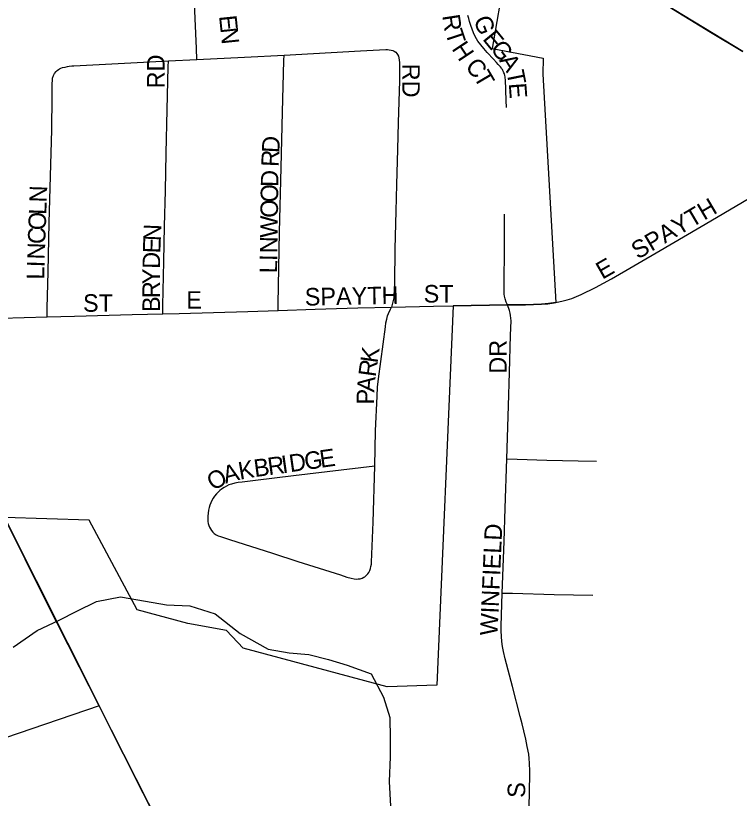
# Model space of a CAD drawing. Extents: x 0 to 34, y 0 to 22.
# Drawn here: x 6.1227 to 6.3183, y 17.9272 to 18.1386 of the extents above; entities that cross this region are included whole.
import ezdxf

# ---------------------------------------------------------------- set-up
doc = ezdxf.new("R2010")
doc.units = 0
for name, color, linetype in [('Default', 7, 'Continuous'), ('GM_X_City_Street', 7, 'Continuous'), ('GM_X_City_Street_Text', 7, 'Continuous'), ('GM_X_Corporation', 7, 'Continuous'), ('GM_X_County_Road', 7, 'Continuous'), ('GM_X_Minor_River', 7, 'Continuous'), ('GM_X_State_Route', 7, 'Continuous'), ('GM_X_Township_Subdivision', 7, 'Continuous'), ('GM_X_Township_Subdivision_Text', 7, 'Continuous')]:
    doc.layers.add(name, color=color, linetype=linetype)

msp = doc.modelspace()

# ---------------------------------------------------------------- linework, layer by layer
at = {"layer": 'Default'}
msp.add_lwpolyline([(6.21175, 17.82109), (6.19182, 17.86034), (6.14526, 17.95216), (6.11969, 18.00306), (6.11076, 18.02099), (6.07084, 18.10026), (6.06147, 18.11896), (6.05496, 18.13197), (6.04884, 18.14072), (6.02545, 18.17135), (6.01014, 18.19175), (5.98748, 18.22193), (5.95849, 18.26057), (5.9573, 18.26217)], dxfattribs=at)
at = {"layer": 'GM_X_City_Street'}
for points in [[(6.17167, 18.12678), (6.17156, 18.12969), (6.17107, 18.14192), (6.17077, 18.15276), (6.17063, 18.15636)], [(6.25541, 18.11379), (6.25532, 18.11573), (6.25509, 18.12137), (6.25506, 18.12171), (6.25501, 18.12205), (6.25494, 18.12243), (6.25481, 18.12285), (6.25469, 18.12314), (6.25456, 18.12344), (6.2544, 18.12379), (6.25426, 18.12404), (6.25412, 18.12427), (6.254, 18.12445), (6.25377, 18.12474), (6.25313, 18.12545), (6.25266, 18.12597), (6.25187, 18.12682), (6.25019, 18.12865), (6.24924, 18.12974), (6.24767, 18.1317), (6.24725, 18.13237), (6.24695, 18.13298), (6.2465, 18.13394), (6.2461, 18.13495), (6.24574, 18.13595), (6.24538, 18.137), (6.24516, 18.13786), (6.24496, 18.13869)], [(6.19525, 18.12796), (6.21596, 18.12909), (6.22102, 18.12938), (6.22275, 18.12946), (6.22323, 18.12944), (6.22368, 18.1294), (6.22418, 18.12932), (6.22464, 18.12917), (6.22506, 18.12899), (6.22543, 18.12874), (6.22576, 18.12841), (6.22596, 18.12808), (6.22617, 18.12765), (6.22628, 18.1272), (6.2264, 18.12662), (6.22648, 18.12594), (6.2265, 18.12439), (6.22643, 18.12097), (6.22608, 18.10976), (6.22592, 18.10245), (6.22567, 18.09298), (6.22547, 18.08575), (6.22521, 18.07557), (6.22507, 18.06638), (6.22495, 18.06289), (6.2249, 18.06235), (6.22478, 18.06165), (6.22432, 18.05988)], [(6.17167, 18.12678), (6.18457, 18.12741), (6.19525, 18.12796)], [(6.19363, 18.05896), (6.19366, 18.06074), (6.19404, 18.0801), (6.19448, 18.09758), (6.19482, 18.11254), (6.19521, 18.12645), (6.19525, 18.12796)], [(6.13118, 18.05725), (6.13123, 18.05961), (6.13146, 18.06938), (6.13178, 18.08262), (6.13215, 18.09528), (6.13244, 18.10779), (6.13255, 18.11667), (6.13255, 18.12037), (6.13262, 18.12103), (6.13268, 18.12168), (6.13292, 18.12247), (6.13324, 18.123), (6.13368, 18.12353), (6.13396, 18.1238), (6.13428, 18.12403), (6.13458, 18.12422), (6.13494, 18.1244), (6.1354, 18.12456), (6.13605, 18.12473), (6.13668, 18.12485), (6.13721, 18.12493), (6.13789, 18.12502), (6.13843, 18.12506), (6.15558, 18.12597), (6.164, 18.12641)], [(6.16247, 18.05805), (6.1625, 18.06034), (6.16274, 18.07222), (6.16297, 18.08172), (6.16319, 18.0913), (6.16339, 18.10146), (6.16369, 18.1132), (6.16396, 18.12481), (6.164, 18.12641)], [(6.164, 18.12641), (6.17167, 18.12678)], [(6.25562, 18.06045), (6.25532, 18.06118), (6.25499, 18.06209), (6.25483, 18.06279), (6.25479, 18.06333), (6.25488, 18.07846), (6.25481, 18.08494)], [(6.19363, 18.05896), (6.20364, 18.05927), (6.21523, 18.05966), (6.22432, 18.05988)], [(6.21975, 18.01694), (6.22001, 18.02642), (6.22038, 18.03583), (6.22055, 18.03826), (6.22075, 18.04048), (6.22264, 18.05458), (6.22281, 18.05561), (6.22301, 18.05664), (6.22326, 18.0575), (6.2235, 18.05812), (6.22403, 18.05927), (6.22432, 18.05988)], [(6.22432, 18.05988), (6.23566, 18.06016), (6.24095, 18.06026)], [(6.09569, 18.05096), (6.09827, 18.05222), (6.10041, 18.05326), (6.10209, 18.05398), (6.1039, 18.05469), (6.10489, 18.05501), (6.106, 18.05534), (6.10711, 18.05563), (6.10817, 18.05584), (6.11097, 18.05625), (6.11397, 18.05662), (6.11628, 18.05679), (6.11874, 18.05687), (6.13118, 18.05725)], [(6.13118, 18.05725), (6.1386, 18.05741), (6.1542, 18.05783), (6.16247, 18.05805)], [(6.16247, 18.05805), (6.1669, 18.05818), (6.18544, 18.0587), (6.19363, 18.05896)], [(6.21975, 18.01694), (6.19777, 18.01428), (6.18749, 18.01306), (6.18392, 18.01261), (6.18289, 18.01247), (6.18194, 18.01228), (6.18109, 18.01208), (6.18037, 18.01183), (6.17967, 18.01152), (6.17906, 18.01117), (6.17837, 18.0107), (6.17787, 18.01031), (6.17735, 18.00981), (6.17697, 18.0094), (6.17646, 18.00881), (6.1761, 18.00827), (6.17572, 18.00759), (6.17545, 18.00702), (6.17521, 18.0064), (6.17502, 18.00576), (6.17486, 18.00506), (6.17474, 18.00416), (6.17465, 18.00336), (6.17464, 18.0025), (6.17467, 18.00192), (6.17476, 18.00138), (6.17491, 18.00085), (6.17511, 18.00038), (6.17537, 17.99994), (6.17564, 17.99951), (6.17597, 17.9991), (6.17639, 17.99873), (6.17689, 17.99838), (6.17743, 17.99812), (6.17804, 17.99789), (6.1805, 17.99712), (6.19212, 17.99337), (6.19895, 17.99119), (6.21047, 17.98752), (6.21224, 17.98696), (6.21343, 17.98662), (6.21422, 17.98649), (6.21476, 17.98642), (6.21533, 17.98645), (6.2158, 17.98651), (6.21637, 17.98669), (6.21679, 17.98689), (6.21707, 17.98704), (6.21738, 17.98727), (6.21765, 17.98754), (6.2179, 17.98783), (6.21814, 17.98822), (6.21841, 17.98871), (6.21862, 17.98924), (6.21875, 17.98978), (6.21886, 17.99042), (6.21891, 17.99097), (6.21932, 18.00175), (6.21975, 18.01694)]]:
    msp.add_lwpolyline(points, dxfattribs=at)
at = {"layer": 'GM_X_Corporation'}
msp.add_lwpolyline([(6.3193, 18.12893), (6.3007, 18.14021), (6.2649, 18.16289), (6.25482, 18.14911), (6.2515, 18.12969), (6.26528, 18.12708), (6.26522, 18.12282), (6.26874, 18.06114), (6.26677, 18.06089), (6.2648, 18.06064), (6.26054, 18.06052), (6.25562, 18.06045), (6.24095, 18.06026), (6.23658, 17.95776), (6.22313, 17.95729), (6.18424, 17.9677), (6.17972, 17.97255), (6.16927, 17.97439), (6.15554, 17.97807), (6.14257, 18.00229), (6.11969, 18.00306), (6.14526, 17.95216), (6.10876, 17.93971), (6.10567, 17.89838)], dxfattribs=at)
at = {"layer": 'GM_X_County_Road'}
msp.add_lwpolyline([(6.2649, 18.16289), (6.27524, 18.15656), (6.28855, 18.14804), (6.30054, 18.14031), (6.31054, 18.13411), (6.3193, 18.12893)], dxfattribs=at)
at = {"layer": 'GM_X_Minor_River'}
msp.add_lwpolyline([(6.12207, 17.96797), (6.12856, 17.97248), (6.13446, 17.97528), (6.13922, 17.97771), (6.14455, 17.98033), (6.15101, 17.9816), (6.15784, 17.98041), (6.16352, 17.97942), (6.16978, 17.97919), (6.17659, 17.97705), (6.18339, 17.97168), (6.19094, 17.96745), (6.19663, 17.96646), (6.20194, 17.96604), (6.20724, 17.96467), (6.21235, 17.96312), (6.21879, 17.96079), (6.22216, 17.95451), (6.22382, 17.94899), (6.22397, 17.9433), (6.22394, 17.93836), (6.2237, 17.93172), (6.22403, 17.92508)], dxfattribs=at)
at = {"layer": 'GM_X_State_Route'}
msp.add_lwpolyline([(6.19182, 17.86034), (6.18336, 17.87709), (6.17266, 17.89814), (6.16834, 17.90664), (6.1572, 17.92853), (6.15186, 17.93906), (6.14526, 17.95216), (6.13993, 17.96261), (6.13086, 17.98053), (6.11969, 18.00306)], dxfattribs=at)
at = {"layer": 'GM_X_Township_Subdivision'}
for points in [[(6.26874, 18.06114), (6.27069, 18.06153), (6.27179, 18.06183), (6.27303, 18.06221), (6.27431, 18.0627), (6.27557, 18.06325), (6.27946, 18.06514), (6.2838, 18.06751), (6.29696, 18.07515), (6.31062, 18.08317), (6.32266, 18.09025), (6.3307, 18.09497), (6.339, 18.09985), (6.35215, 18.1075), (6.35441, 18.10882)], [(6.24095, 18.06026), (6.25562, 18.06045)], [(6.25548, 18.01891), (6.25593, 18.03322), (6.25618, 18.04223), (6.2565, 18.05226), (6.25663, 18.05616), (6.25658, 18.05691), (6.2565, 18.05756), (6.25638, 18.05826), (6.25617, 18.05892), (6.25562, 18.06045)], [(6.25562, 18.06045), (6.26054, 18.06052), (6.26481, 18.06064), (6.2666, 18.0608), (6.26829, 18.06104), (6.26874, 18.06114)], [(6.2542, 17.98263), (6.25471, 17.99658), (6.25503, 18.00555), (6.25548, 18.01891)], [(6.25548, 18.01891), (6.2583, 18.01881), (6.26628, 18.01852), (6.27479, 18.01832), (6.27968, 18.01824)], [(6.26126, 17.91735), (6.2616, 17.92828), (6.26169, 17.93451), (6.26163, 17.93671), (6.26155, 17.93791), (6.26138, 17.93914), (6.26101, 17.94115), (6.2606, 17.94313), (6.26006, 17.94539), (6.25961, 17.94732), (6.25912, 17.94927), (6.25696, 17.95739), (6.25498, 17.96488), (6.25455, 17.96685), (6.2543, 17.96819), (6.25414, 17.96957), (6.25403, 17.97093), (6.25393, 17.9724), (6.25394, 17.9737), (6.2542, 17.98263)], [(6.2542, 17.98263), (6.25699, 17.98256), (6.2683, 17.98227), (6.27874, 17.98207)]]:
    msp.add_lwpolyline(points, dxfattribs=at)

# ---------------------------------------------------------------- texts
at = {"layer": 'GM_X_City_Street_Text'}
for s, height, rotation, p in [('E', 0.00473, 275.9318, (6.17767, 18.1385)), ('R', 0.00473, 278.7767, (6.238, 18.1386)), ('G', 0.00473, 291.1801, (6.2464, 18.13754)), ('T', 0.00473, 288.3304, (6.23877, 18.13406)), ('N', 0.00473, 275.9106, (6.17802, 18.13519)), ('E', 0.00473, 309.2777, (6.24873, 18.13225)), ('H', 0.00473, 303.5366, (6.24042, 18.12966)), ('G', 0.00473, 307.7005, (6.25082, 18.1297)), ('RD', 0.004735, 90, (6.16295, 18.11896)), ('A', 0.00473, 302.2533, (6.25329, 18.1265)), ('RD', 0.004735, 270, (6.22721, 18.12563)), ('C', 0.00473, 312.0808, (6.24399, 18.12461)), ('T', 0.00473, 300.3921, (6.24635, 18.12204)), ('T', 0.00473, 281.3849, (6.25535, 18.1234)), ('E', 0.00473, 274.2394, (6.25599, 18.12029)), ('D', 0.00473, 87.1572, (6.19395, 18.10143)), ('R', 0.00473, 87.522, (6.19379, 18.09769)), ('D', 0.00473, 89.0819, (6.19369, 18.09231)), ('N', 0.00473, 87.9889, (6.13109, 18.08808)), ('O', 0.00473, 89.1595, (6.19363, 18.08814)), ('L', 0.00473, 87.978, (6.13097, 18.08474)), ('O', 0.00473, 89.1595, (6.19357, 18.08398)), ('O', 0.00473, 87.9889, (6.13083, 18.08058)), ('W', 0.00473, 89.1594, (6.19349, 18.07856)), ('C', 0.00473, 87.984, (6.13069, 18.07683)), ('N', 0.00473, 87.7041, (6.16192, 18.07766)), ('E', 0.00473, 87.7869, (6.16179, 18.07433)), ('N', 0.00473, 89.1595, (6.19343, 18.07439)), ('N', 0.00473, 88.0326, (6.13055, 18.07267)), ('D', 0.00473, 88.8853, (6.16171, 18.07019)), ('L', 0.00473, 89.153, (6.19335, 18.06898)), ('I', 0.00473, 89.1498, (6.1934, 18.07231)), ('L', 0.00473, 89.1257, (6.13043, 18.06728)), ('I', 0.00473, 88.1637, (6.13048, 18.07059)), ('Y', 0.00473, 89.9688, (6.16171, 18.06605)), ('R', 0.00473, 89.9687, (6.1617, 18.0623)), ('ST', 0.004735, 0, (6.23299, 18.06111)), ('E', 0.00473, 0, (6.16883, 18.05944)), ('SPAYTH', 0.004735, 1.0603, (6.20089, 18.06027)), ('ST', 0.004735, 0, (6.14091, 18.05861)), ('B', 0.00473, 89.9757, (6.1617, 18.05855)), ('K', 0.00473, 81.8853, (6.22051, 18.04457)), ('R', 0.00473, 82.0073, (6.21999, 18.04086)), ('A', 0.00473, 84.8788, (6.21962, 18.03677)), ('P', 0.00473, 89.5082, (6.2196, 18.03354)), ('E', 0.00473, 8.1633, (6.20519, 18.01644)), ('B', 0.00473, 7.4293, (6.18738, 18.01395)), ('R', 0.00473, 7.9507, (6.19114, 18.01444)), ('I', 0.00473, 8.1789, (6.19487, 18.01496)), ('D', 0.00473, 8.1363, (6.19694, 18.01526)), ('G', 0.00473, 8.1578, (6.20106, 18.01585)), ('A', 0.00473, 15.2609, (6.17942, 18.01216)), ('K', 0.00473, 10.127, (6.18333, 18.01323)), ('O', 0.00473, 31.871, (6.17621, 18.0101))]:
    msp.add_text(s, height=height, rotation=rotation, dxfattribs=at).set_placement(p)
at = {"layer": 'GM_X_Township_Subdivision_Text'}
for s, height, rotation, p in [('SPAYTH', 0.004735, 30.5075, (6.2909, 18.07266)), ('E', 0.00473, 29.7314, (6.2813, 18.06724)), ('DR', 0.004735, 90, (6.25544, 18.04188)), ('WINFIELD', 0.004735, 87.4746, (6.25294, 17.97107)), ('S', 0.00473, 90, (6.26043, 17.9273))]:
    msp.add_text(s, height=height, rotation=rotation, dxfattribs=at).set_placement(p)

doc.saveas('drawing.dxf')
